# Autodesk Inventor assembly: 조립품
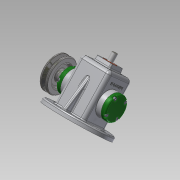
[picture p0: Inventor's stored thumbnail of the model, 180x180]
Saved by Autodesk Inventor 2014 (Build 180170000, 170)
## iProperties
Created: 2017-07
Part Number: 조립품
Document SubType Name: Assembly
Designer: user
Author: user
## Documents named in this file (16)
- C:\Users\user\Desktop\470708V1012\조립품.iam
- C:\Users\user\Desktop\470708V1012\V벨트풀리.ipt
- C:\Users\user\Desktop\470708V1012\고정핀 1.2 x  8.ipt
- C:\Users\user\Desktop\470708V1012\뒤커버.ipt
- C:\Users\user\Desktop\470708V1012\링크.ipt
- C:\Users\user\Desktop\470708V1012\멈춤나사 M3x8.ipt
- C:\Users\user\Desktop\470708V1012\베어링 12 x 32 x 10.ipt
- C:\Users\user\Desktop\470708V1012\본체.ipt
- C:\Users\user\Desktop\470708V1012\볼트 M4 x 12.ipt
- C:\Users\user\Desktop\470708V1012\부시.ipt
- C:\Users\user\Desktop\470708V1012\슬라이드.ipt
- C:\Users\user\Desktop\470708V1012\앞커버.ipt
- C:\Users\user\Desktop\470708V1012\오일실 12 25 7.ipt
- C:\Users\user\Desktop\470708V1012\키 4 x 4 x 10.ipt
- C:\Users\user\Desktop\470708V1012\편심축.ipt
- C:\Users\user\Desktop\470708V1012\핀 5 x 18.ipt
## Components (3 placed, 3 different names)
1. V벨트풀리:2
2. 고정핀 1.2 x  8:2 — 플러쉬:1
3. 핀 5 x 18:2
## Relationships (1: Flush 1)
- 플러쉬:1 [Flush]: 고정핀 1.2 x  8:2
